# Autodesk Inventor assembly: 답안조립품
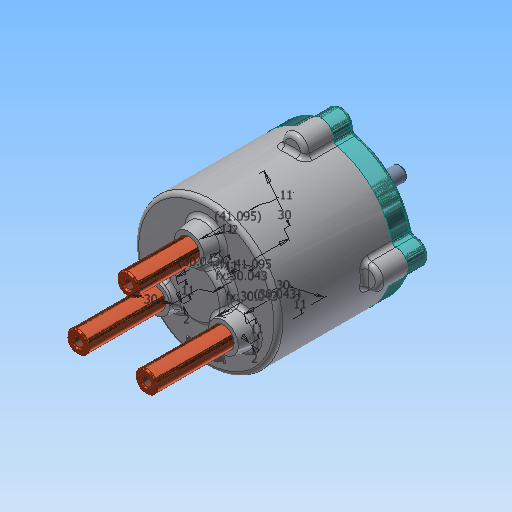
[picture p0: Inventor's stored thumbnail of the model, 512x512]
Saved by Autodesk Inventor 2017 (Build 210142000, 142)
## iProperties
Part Number: 답안조립품
Material: 일반
Document SubType Name: Assembly
Designer: MRC
Author: MRC
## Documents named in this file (14)
- C:\Users\MRC\Desktop\610708V1004\답안조립품.iam
- C:\Users\MRC\Desktop\610708V1004\본체.ipt
- C:\Users\MRC\Desktop\610708V1004\가변스프링1.ipt
- C:\Users\MRC\Desktop\610708V1004\가변스프링2.ipt
- C:\Users\MRC\Desktop\610708V1004\가변스프링3.ipt
- C:\Users\MRC\Desktop\610708V1004\멈춤링 10 x 1.ipt
- C:\Users\MRC\Desktop\610708V1004\멈춤링 22 x 1.2.ipt
- C:\Users\MRC\Desktop\610708V1004\메인 축.ipt
- C:\Users\MRC\Desktop\610708V1004\베어링 NA 4900.ipt
- C:\Users\MRC\Desktop\610708V1004\볼트 M5.ipt
- C:\Users\MRC\Desktop\610708V1004\슬라이드 축.ipt
- C:\Users\MRC\Desktop\610708V1004\오일실.ipt
- C:\Users\MRC\Desktop\610708V1004\커버.ipt
- C:\Users\MRC\Desktop\610708V1004\판캠.ipt
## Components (3 placed, 3 different names)
1. 가변스프링3:1
2. 가변스프링1:1
3. 가변스프링2:1
